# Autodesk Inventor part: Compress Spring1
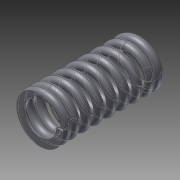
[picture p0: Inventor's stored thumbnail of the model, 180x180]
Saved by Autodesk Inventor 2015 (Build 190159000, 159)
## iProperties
Created: 2014-07
Part Number: Compress Spring1
Material: Steel
Document SubType Name: Modeling
Designer: User
Density: 2.18 g/cm^3
Appearance: Steel
CustomPartVersion: 1
Author: User
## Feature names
1. Main Coil Feature(R)
2. Start Transition Coil 1(Right)
3. Coil  Start Transition 2(R)
4. Coil  Start Transition 3(R)
5. Coil  Start Transition 4(R)
6. Start Ends Coil(Right)
7. Start Cut Feature(Right) [Extrusion]
8. End Transition Coil 1(Right)
9. End Transition Coil 2(Right)
10. End Transition Coil 3(Right)
11. End Transition Coil 4(Right)
12. End Coil(Right)
13. End Cut Feature(Right) [Extrusion]
14. Plain Ends Cut Feature 1(Right) [Extrusion]
15. Plain Ends Cut  2(R) [Extrusion]
16. Main Coil Feature(L)
17. Start Transition Coil 1(Left)
18. Start Transition Coil 2(Left)
19. Start Transition Coil 3(Left)
20. Start Transition Coil 4(Left)
21. Start Ends Coil(Left)
22. Start Cut Feature(Left) [Extrusion]
23. End Transition Coil 1(Left)
24. End Transition Coil 2(Left)
25. End Transition Coil 3(Left)
26. End Transition Coil 4(Left)
27. End Coil(Left)
28. End Cut Feature(Left) [Extrusion]
29. Cut Plain Ends Cut 1(L) [Extrusion]
30. Cut Plain Ends Cut 2(L) [Extrusion]
## Parameters: d0 = 0.3125 mm, da_d = 1.25 mm, da_D2 = 5 mm, da_ti = 2.00104 mm, da_nz1 = 15 mm, spiral_Angle = 1.01562 mm, d2 = 2.00104 mm, d4 = 52.5 mm, d5 = 0, d6 = 90 deg, d7 = 90 deg, d8 = 0, d9 = 0, d12 = 2.39875 mm, d13 = -3.09578 mm, d14 = 1.25 mm, d15 = 0, d16 = 1.81328 mm, d18 = 2.5 mm, d19 = 0, d20 = 90 deg, d21 = 90 deg, d22 = 0, d23 = 0, d24 = 1.62552 mm, d26 = 2.5 mm, d27 = 0, d28 = 90 deg, d29 = 90 deg, d30 = 0, d31 = 0, d32 = 1.43776 mm, d34 = 2.5 mm, d35 = 0, d36 = 90 deg, d37 = 90 deg, d38 = 0, d39 = 0, d40 = 1.25 mm, d42 = 2.5 mm, d43 = 0, d44 = 90 deg, d45 = 90 deg, d46 = 0, d47 = 0, d48 = 1.81328 mm, d50 = 1.875 mm, d51 = 0, d52 = 90 deg, d53 = 90 deg, d54 = 0, d55 = 0, d56 = 1.62552 mm, d58 = 1.875 mm, d59 = 0, d60 = 90 deg, d61 = 90 deg, d62 = 0, d63 = 0, d64 = 1.43776 mm, d66 = 1.875 mm, d67 = 0, d68 = 90 deg, d69 = 90 deg, d70 = 0, d71 = 0, d72 = 1.25 mm, d74 = 1.875 mm, d75 = 0, d76 = 90 deg, d77 = 90 deg, d78 = 0, d79 = 0, End_Pitch = 1.25647 mm, d82 = 15 mm, d83 = 0, d84 = 90 deg, d85 = 90 deg, d86 = 0, d87 = 0, d88 = 1.25647 mm, d91 = 0, d92 = 90 deg, d93 = 90 deg, d94 = 0, d95 = 0, d96 = 7.5 mm, d97 = 1.25647 mm, d98 = 0, d99 = 7.5 mm, d100 = 1.25647 mm, d101 = 0, d102 = 0, d103 = 0, d104 = 0, d105 = 0, d106 = 0, d108 = 0, d112 = 0, d113 = 0, d114 = 0, const_zero = 0, Not_rightdir = 0, d121 = 0.32058 mm, d131 = 0, d132 = 0, d133 = 0, d134 = 0, d135 = 0.3125 mm, d137 = 2.00104 mm, d139 = 52.5 mm, d140 = 0, d141 = 90 deg, d142 = 90 deg, d143 = 0, d144 = 0, d145 = 2.39875 mm, d146 = -3.09578 mm, d147 = 0.32058 mm, d148 = 0.00646 mm, d149 = 1.25 mm, d150 = 0, d151 = 0, d152 = 1.81328 mm, d154 = 2.5 mm, d155 = 0, d156 = 90 deg, d157 = 90 deg, d158 = 0, d159 = 0, d160 = 1.62552 mm, d162 = 2.5 mm, d163 = 0, d164 = 90 deg, d165 = 90 deg, d166 = 0, d167 = 0, d168 = 1.43776 mm, d170 = 2.5 mm, d171 = 0, d172 = 90 deg, d173 = 90 deg, d174 = 0, d175 = 0, d176 = 1.25 mm, d178 = 2.5 mm, d179 = 0, d180 = 90 deg, d181 = 90 deg, d182 = 0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
